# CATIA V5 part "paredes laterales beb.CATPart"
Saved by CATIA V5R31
Part number: paredes laterales beb
Bounding box of the stored display mesh (mm): x -131.8 to 135.1, y -100 to 100, z 0 to 3.3
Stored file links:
  C:\Users\189361\Desktop\paredes laterales beb.CATPart
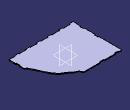
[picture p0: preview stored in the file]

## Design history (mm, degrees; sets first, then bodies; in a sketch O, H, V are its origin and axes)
Set1 "sketch"
  Sketch1 on xy-plane, origin (0, 0, 0), H (1, 0, 0), V (0, 1, 0)
    line L1 (108.6, -100) -> (92.8, -100)
    line L2 (-131.8, -100) -> (-131.8, 100)
    line L3 (-131.8, 100) -> (22.7, 100)
    point P1 (127.0145, 50)
    point P3 (-131.8, 100)
    construction line L4 (-131.8, 18.8983) -> (-116.8, 18.8983)
    point P4 (-131.8, 18.8983)
    point P5 (-116.8, 18.8983)
    construction line L5 (-116.8, 18.8983) -> (-86.8, 18.8983)
    construction line L6 (-86.8, 18.8983) -> (-71.8, 18.8983)
    point P7 (-71.8, 18.8983)
    construction line L7 (-71.8, 18.8983) -> (-41.8, 18.8983)
    construction line L8 (-41.8, 18.8983) -> (-26.8, 18.8983)
    point P9 (-26.8, 18.8983)
    construction line L9 (-26.8, 18.8983) -> (3.2, 18.8983)
    construction line L10 (3.2, 18.8983) -> (18.2, 18.8983)
    construction line L11 (18.2, 18.8983) -> (48.2, 18.8983)
    construction line L12 (48.2, 18.8983) -> (63.2, 18.8983)
    point P13 (63.2, 18.8983)
    construction line L13 (63.2, 18.8983) -> (93.2, 18.8983)
    construction line L14 (93.2, 18.8983) -> (108.2, 18.8983)
    point P15 (108.2, 18.8983)
    point P16 (-116.4, -96.7)
    line L15 (-116.4, -96.7) -> (-87.2, -96.7)
    point P17 (-87.2, -96.7)
    line L16 (-87.2, -96.7) -> (-87.2, -100)
    point P18 (-87.2, -100)
    line L17 (-116.4, -96.7) -> (-116.4, -100)
    point P19 (-116.4, -100)
    line L18 (-116.4, -100) -> (-131.8, -100)
    point P20 (-71.4, -100)
    line L19 (-71.4, -100) -> (-71.4, -96.7)
    point P21 (-71.4, -96.7)
    line L20 (-71.4, -96.7) -> (-42.2, -96.7)
    point P22 (-42.2, -96.7)
    line L21 (-42.2, -96.7) -> (-42.2, -100)
    point P23 (-42.2, -100)
    construction line L22 (-34.3, -26.5545) -> (-34.3, -6.5428)
    line L23 (-71.4, -100) -> (-87.2, -100)
    point P26 (47.8, -100)
    point P27 (47.8, -96.7)
    line L24 (47.8, -96.7) -> (47.8, -100)
    point P28 (18.6, -96.7)
    line L25 (47.8, -96.7) -> (18.6, -96.7)
    point P29 (18.6, -100)
    line L26 (18.6, -96.7) -> (18.6, -100)
    point P30 (2.8, -96.7)
    point P31 (2.8, -100)
    line L27 (2.8, -100) -> (2.8, -96.7)
    point P32 (-26.4, -96.7)
    line L28 (2.8, -96.7) -> (-26.4, -96.7)
    point P33 (-26.4, -100)
    line L29 (-26.4, -96.7) -> (-26.4, -100)
    line L30 (-26.4, -100) -> (-42.2, -100)
    line L31 (18.6, -100) -> (2.8, -100)
    construction line L32 (55.7, -38.7089) -> (55.7, 49.8488)
    point P36 (92.8, -96.7)
    point P37 (63.6, -96.7)
    line L33 (63.6, -96.7) -> (92.8, -96.7)
    point P38 (108.6, -96.7)
    point P39 (108.6, -100)
    line L34 (108.6, -100) -> (108.6, -96.7)
    point P40 (92.8, -100)
    line L35 (92.8, -96.7) -> (92.8, -100)
    point P41 (63.6, -100)
    line L36 (63.6, -96.7) -> (63.6, -100)
    line L37 (108.6, -96.7) -> (131.8, -96.7)
    point P42 (131.8, -96.7)
    line L38 (63.6, -100) -> (47.8, -100)
    construction line L39 (-131.8, 100) -> (22.7, 100)
    point P43 (-131.8, 100)
    construction line L40 (127.0145, 50) -> (127.0145, -30)
    point P45 (127.0145, -30)
    line L41 (22.7, 100) -> (27.5145, 94)
    point P46 (27.5145, 94)
    point P47 (52.0145, 74)
    line L42 (52.0145, 74) -> (82.201, 54)
    point P48 (82.201, 54)
    line L43 (82.201, 54) -> (97.0145, 34)
    point P49 (97.0145, 34)
    line L44 (97.0145, 34) -> (127.0145, -30)
    axis line L45 (131.8, -96.7) -> (135.1, -96.7)
    point P50 (131.8, -96.7)
    line L46 (135.1, -96.7) -> (135.1, -36.7)
    point P52 (135.1, -36.7)
    line L47 (127.0145, -30) -> (135.1, -36.7)
    line L48 (131.8, -96.7) -> (135.1, -96.7)
    line L49 (27.5145, 94) -> (30.7874, 86.6075)
    point P53 (30.7874, 86.6075)
    line L50 (30.7874, 86.6075) -> (48.4133, 78.9254)
    point P54 (48.4133, 78.9254)
    line L51 (48.4133, 78.9254) -> (52.0145, 74)
    length L2 = 200
    length L4 = 15
    length L5 = 30
    length L6 = 15
    length L7 = 30
    length L8 = 15
    length L9 = 30
    length L10 = 15
    length L11 = 30
    length L12 = 15
    length L13 = 30
    length L14 = 15
    length L15 = 29.2
    length L16 = 3.3
    distance L17 P5 = 0.4
    length L20 = 29.2
    distance P7 L19 = 0.4
    distance L22 P9 = 7.5
    distance L32 P13 = 7.5
    length L39 = 154.5
    length L40 = 80
    distance P46 P47 V = 20
    distance P48 P47 V = 20
    distance P48 P49 V = 20
    distance P3 P1 = 263.6
    length L45 = 3.3
    length L46 = 60
    distance P52 P45 V = 6.7
    distance P42 L2 = 263.6
    distance V L2 = 131.8
    distance P47 L40 = 75
    distance P48 L40 = 44.8136
    distance P49 L40 = 30
    distance P46 L3 = 6
    angle L49 L50 = 137.4302
    angle L50 L51 = 149.7222
    distance P53 P46 V = 7.3925
    distance P54 P47 = 6.1014
    vertical: L2 V, L16 V, L17 V, L19 V, L21 V, L22 V, L32 V, L40 V, L46 V
    horizontal: L3 H, L1 H, L4 H, L5 H, L6 H, L7 H, L8 H, L9 H, L10 H, L11 H, L12 H, L13 H, L14 H, L15 H, L18 H, L20 H, L23 H, L30 H, L31 H, L37 H, L38 H, L39 H, L45 H, L48 H
    equidistance: L1 L3 O
    coincidence: P4 L2, P19 L1, L1 L18, P20 L1, L1 L23, L1 L30, L1 L31, L1 L38, P43 L2, L39 L3, L41 P45, L43 P15, P50 P42
    equal size: L21 L16
    symmetry: P19 P26 L22, P16 P27 L22, L17 L24 L22, P17 P28 L22, L15 L25 L22, P18 P29 L22, L16 L26 L22, P21 P30 L22, P20 P31 L22, L19 L27 L22, P22 P32 L22, L20 L28 L22, P23 P33 L22, L21 L29 L22, P28 P36 L32, P27 P37 L32, L25 L33 L32, P30 P38 L32, P31 P39 L32, L27 L34 L32, P29 P40 L32, L26 L35 L32, P26 P41 L32, L24 L36 L32
  Sketch2 on end face of Pad1, origin (0, 0, 3.3), H (1, 0, 0), V (0, 1, 0)
    point P1 (-131.8, -54.2)
    line L1 (-131.8, -54.2) -> (-128.5, -54.2)
    point P2 (-128.5, -54.2)
    line L2 (-128.5, -54.2) -> (-128.5, -69.2)
    point P3 (-128.5, -69.2)
    line L3 (-128.5, -69.2) -> (-131.8, -69.2)
    point P4 (-131.8, -69.2)
    line L4 (-131.8, -69.2) -> (-131.8, -54.2)
    construction line L5 (-175.5784, -61.7) -> (-220.4038, -61.7)
    reference projected line E1 (-116.4, -96.7) -> (-87.2, -96.7) from edge [face of Pad1 from Sketch1.L15 | end face of Pad1]
    reference projected line E2 (-131.8, 100) -> (-131.8, -100) from edge [face of Pad1 from Sketch1.L2 | end face of Pad1]
    line L6 (131.8, -54.2) -> (135.1, -54.2)
    line L7 (135.1, -54.2) -> (135.1, -69.2)
    line L8 (135.1, -69.2) -> (131.8, -69.2)
    line L9 (131.8, -69.2) -> (131.8, -54.2)
    reference projected line E3 (135.1, -96.7) -> (135.1, -36.7) from edge [face of Pad1 from Sketch1.L46 | end face of Pad1]
    construction line L10 (-112.54, -31.7) -> (-72.5761, -31.7)
    point P13 (-131.8, -9.2)
    point P14 (-128.5, -9.2)
    point P15 (-128.5, 5.8)
    point P16 (-131.8, 5.8)
    line L11 (-131.8, -9.2) -> (-128.5, -9.2)
    line L12 (-128.5, -9.2) -> (-128.5, 5.8)
    line L13 (-128.5, 5.8) -> (-131.8, 5.8)
    line L14 (-131.8, 5.8) -> (-131.8, -9.2)
    point P17 (-119.3, 100)
    line L15 (-119.3, 100) -> (-104.3, 100)
    point P18 (-104.3, 100)
    line L16 (-104.3, 100) -> (-104.3, 96.7)
    point P19 (-104.3, 96.7)
    line L17 (-104.3, 96.7) -> (-119.3, 96.7)
    point P20 (-119.3, 96.7)
    line L18 (-119.3, 96.7) -> (-119.3, 100)
    construction line L19 (-111.8, 109.075) -> (-111.8, 136.0215)
    axis line L20 (-81.8, 112.6261) -> (-81.8, 152.1058)
    point P25 (-44.3, 100)
    point P26 (-59.3, 100)
    point P27 (-59.3, 96.7)
    point P28 (-44.3, 96.7)
    line L21 (-44.3, 100) -> (-59.3, 100)
    line L22 (-59.3, 100) -> (-59.3, 96.7)
    line L23 (-59.3, 96.7) -> (-44.3, 96.7)
    line L24 (-44.3, 96.7) -> (-44.3, 100)
    reference projected line E4 (22.7, 100) -> (-131.8, 100) from edge [face of Pad1 from Sketch1.L3 | end face of Pad1]
    length L4 = 15
    length L1 = 3.3
    distance L5 L1 = 7.5
    distance L5 E1 = 35
    distance L6 L5 = 7.5
    distance L5 L10 = 30
    distance L16 L19 = 7.5
    length L15 = 15
    length L18 = 3.3
    distance L19 E2 = 20
    distance L19 L20 = 30
    horizontal: L1 H, L3 H, L5 H, L6 H, L8 H, L10 H, L15 H, L17 H
    vertical: L2 V, L4 V, L7 V, L9 V, L16 V, L18 V, L19 V, L20 V
    coincidence: L4 E2, L7 E3, L15 E4
    equal size: L6 L1, L2 L9
    symmetry: P1 P13 L10, P2 P14 L10, P3 P15 L10, P4 P16 L10, L1 L11 L10, L2 L12 L10, L3 L13 L10, L4 L14 L10, P17 P25 L20, P18 P26 L20, P19 P27 L20, P20 P28 L20, L15 L21 L20, L16 L22 L20, L17 L23 L20, L18 L24 L20
Body1 (main body)
  Pad1: profile Sketch1, direction (0, 0, 1), length 3.3
  Fillet1: radius 3, on edge [face of Pad1 from Sketch1.L3 | face of Pad1 from Sketch1.L41]; edge [face of Pad1 from Sketch1.L41 | face of Pad1 from Sketch1.L49]; edge [face of Pad1 from Sketch1.L49 | face of Pad1 from Sketch1.L50]; edge [face of Pad1 from Sketch1.L50 | face of Pad1 from Sketch1.L51]; edge [face of Pad1 from Sketch1.L51 | face of Pad1 from Sketch1.L42]; edge [face of Pad1 from Sketch1.L42 | face of Pad1 from Sketch1.L43]; edge [face of Pad1 from Sketch1.L43 | face of Pad1 from Sketch1.L44]; edge [face of Pad1 from Sketch1.L44 | face of Pad1 from Sketch1.L47]; edge [face of Pad1 from Sketch1.L47 | face of Pad1 from Sketch1.L46]
  Pocket1: profile Sketch2, direction (0, 0, -1), length 3.3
